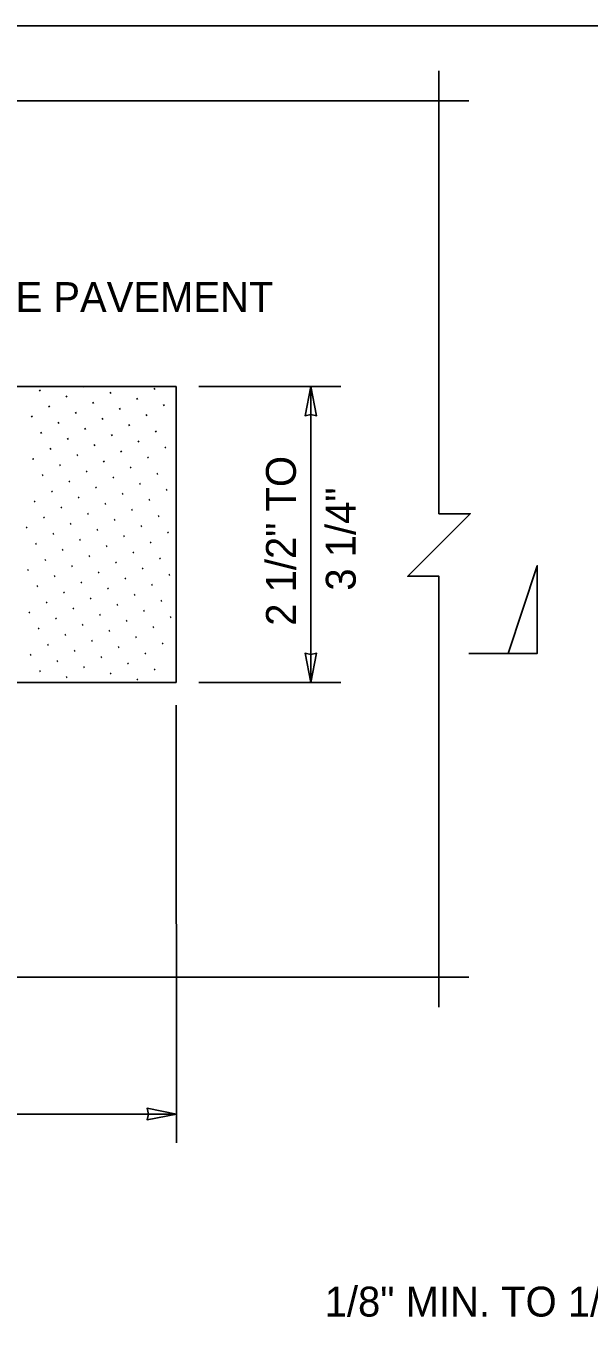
# Model space of a CAD drawing. Extents: x 99862 to 104211, y 98939 to 105076.
# Drawn here: x 102415 to 102716, y 104381 to 105076 of the extents above; entities that cross this region are included whole.
import ezdxf

# ---------------------------------------------------------------- set-up
doc = ezdxf.new("R2010")
doc.units = 0
for name, color, linetype in [('Level 1', 7, 'Continuous'), ('Level 15', 7, 'Continuous'), ('Level 20', 7, 'Continuous'), ('Level 3', 7, 'Continuous'), ('Level 9', 7, 'Continuous')]:
    doc.layers.add(name, color=color, linetype=linetype)

msp = doc.modelspace()

# ---------------------------------------------------------------- linework, layer by layer
at = {"layer": 'Level 1'}
for p, q in [((100264.63, 104882.79), (102495.44, 104882.79)), ((102495.44, 104882.79), (102495.44, 104724.41)), ((102495.44, 104724.41), (100264.63, 104724.41))]:
    msp.add_line(p, q, dxfattribs=at)
msp.add_lwpolyline([(99862, 102999.5), (103151, 102999.5), (103151, 105075.5), (99862, 105075.5)], close=True, dxfattribs=at)
for points in [[(102651.95, 105035.45), (102087.59, 105035.45), (102087.59, 105018.74), (102054.18, 105052.15), (102054.18, 105035.45), (101386.54, 105035.45)], [(102635.95, 105051.45), (102635.95, 104814.69), (102652.65, 104814.69), (102619.25, 104781.28), (102635.95, 104781.28), (102635.95, 104550.9)], [(102651.95, 104566.9), (102017.87, 104566.9), (102017.87, 104550.19), (101984.46, 104583.6), (101984.46, 104566.9), (101386.54, 104566.9)]]:
    msp.add_lwpolyline(points, dxfattribs=at)
at = {"layer": 'Level 15'}
for p, q in [((102507.44, 104882.79), (102583.41, 104882.79)), ((102567.41, 104882.79), (102567.41, 104724.41)), ((102507.44, 104724.41), (102583.41, 104724.41)), ((102495.44, 104712.41), (102495.5, 104478.38)), ((102495.51, 104493.74), (102057.49, 104493.74))]:
    msp.add_line(p, q, dxfattribs=at)
for points in [[(102567.41, 104882.79), (102564.33, 104867.07), (102567.41, 104867.8), (102570.5, 104867.07)], [(102567.41, 104724.41), (102564.33, 104740.13), (102567.41, 104739.41), (102570.5, 104740.13)], [(102495.51, 104493.74), (102479.78, 104490.66), (102480.51, 104493.74), (102479.78, 104496.83)]]:
    msp.add_lwpolyline(points, close=True, dxfattribs=at)
at = {"layer": 'Level 3'}
for p, q in [((102445.68, 104882.52), (102446.15, 104882.79)), ((102483.48, 104881.25), (102484.09, 104881.6)), ((102422.15, 104880.48), (102422.75, 104880.83)), ((102436.41, 104877.17), (102437.02, 104877.52)), ((102459.95, 104879.21), (102460.56, 104879.56)), ((102474.22, 104875.9), (102474.82, 104876.25)), ((102427.15, 104871.82), (102427.75, 104872.17)), ((102441.41, 104868.51), (102442.02, 104868.86)), ((102450.68, 104873.86), (102451.29, 104874.21)), ((102464.95, 104870.55), (102465.56, 104870.9)), ((102479.22, 104867.24), (102479.82, 104867.59)), ((102488.48, 104872.59), (102489.09, 104872.94)), ((102417.88, 104866.47), (102418.48, 104866.82)), ((102432.15, 104863.16), (102432.75, 104863.51)), ((102455.68, 104865.2), (102456.29, 104865.55)), ((102469.95, 104861.89), (102470.56, 104862.24)), ((102422.88, 104857.81), (102423.48, 104858.16)), ((102437.15, 104854.5), (102437.75, 104854.85)), ((102446.41, 104859.85), (102447.02, 104860.2)), ((102460.68, 104856.54), (102461.29, 104856.89)), ((102474.95, 104853.23), (102475.56, 104853.58)), ((102484.22, 104858.58), (102484.82, 104858.93)), ((102427.88, 104849.15), (102428.48, 104849.5)), ((102451.41, 104851.19), (102452.02, 104851.54)), ((102465.68, 104847.88), (102466.29, 104848.23)), ((102489.22, 104849.92), (102489.82, 104850.27)), ((102418.61, 104843.8), (102419.22, 104844.15)), ((102432.88, 104840.49), (102433.48, 104840.84)), ((102442.15, 104845.84), (102442.75, 104846.19)), ((102456.41, 104842.53), (102457.02, 104842.88)), ((102470.68, 104839.22), (102471.29, 104839.57)), ((102479.95, 104844.57), (102480.56, 104844.92)), ((102423.61, 104835.14), (102424.22, 104835.49)), ((102447.15, 104837.18), (102447.75, 104837.53)), ((102461.41, 104833.87), (102462.02, 104834.22)), ((102484.95, 104835.91), (102485.56, 104836.26)), ((102428.61, 104826.48), (102429.22, 104826.83)), ((102437.88, 104831.83), (102438.48, 104832.18)), ((102452.15, 104828.52), (102452.75, 104828.87)), ((102475.68, 104830.56), (102476.29, 104830.91)), ((102489.95, 104827.25), (102490.56, 104827.6)), ((102419.34, 104821.13), (102419.95, 104821.48)), ((102442.88, 104823.17), (102443.48, 104823.52)), ((102457.15, 104819.86), (102457.75, 104820.21)), ((102466.41, 104825.21), (102467.02, 104825.56)), ((102480.68, 104821.9), (102481.29, 104822.25)), ((102424.34, 104812.47), (102424.95, 104812.82)), ((102433.61, 104817.82), (102434.22, 104818.17)), ((102447.88, 104814.51), (102448.48, 104814.86)), ((102471.41, 104816.55), (102472.02, 104816.9)), ((102485.68, 104813.24), (102486.29, 104813.59)), ((102415.08, 104807.12), (102415.68, 104807.47)), ((102438.61, 104809.16), (102439.22, 104809.51)), ((102452.88, 104805.85), (102453.48, 104806.2)), ((102462.15, 104811.2), (102462.75, 104811.55)), ((102476.41, 104807.89), (102477.02, 104808.24)), ((102490.68, 104804.58), (102491.29, 104804.93)), ((102420.08, 104798.46), (102420.68, 104798.81)), ((102429.34, 104803.81), (102429.95, 104804.16)), ((102443.61, 104800.5), (102444.22, 104800.85)), ((102467.15, 104802.54), (102467.75, 104802.89)), ((102481.41, 104799.23), (102482.02, 104799.58)), ((102434.34, 104795.15), (102434.95, 104795.5)), ((102448.61, 104791.84), (102449.22, 104792.19)), ((102457.88, 104797.19), (102458.48, 104797.54)), ((102472.15, 104793.88), (102472.75, 104794.23)), ((102415.81, 104784.45), (102416.41, 104784.8)), ((102425.08, 104789.8), (102425.68, 104790.15)), ((102439.34, 104786.49), (102439.95, 104786.84)), ((102462.88, 104788.53), (102463.48, 104788.88)), ((102477.15, 104785.22), (102477.75, 104785.57)), ((102486.41, 104790.57), (102487.02, 104790.92)), ((102430.08, 104781.14), (102430.68, 104781.49)), ((102444.34, 104777.83), (102444.95, 104778.18)), ((102453.61, 104783.18), (102454.22, 104783.53)), ((102467.88, 104779.87), (102468.48, 104780.22)), ((102491.41, 104781.91), (102492.02, 104782.26)), ((102420.81, 104775.79), (102421.41, 104776.14)), ((102435.08, 104772.48), (102435.68, 104772.83)), ((102458.61, 104774.52), (102459.22, 104774.87)), ((102472.88, 104771.21), (102473.48, 104771.56)), ((102482.15, 104776.56), (102482.75, 104776.91)), ((102425.81, 104767.13), (102426.41, 104767.48)), ((102440.08, 104763.82), (102440.68, 104764.17)), ((102449.34, 104769.17), (102449.95, 104769.52)), ((102463.61, 104765.86), (102464.22, 104766.21)), ((102487.15, 104767.9), (102487.75, 104768.25)), ((102416.54, 104761.78), (102417.15, 104762.13)), ((102430.81, 104758.47), (102431.41, 104758.82)), ((102454.34, 104760.51), (102454.95, 104760.86)), ((102468.61, 104757.2), (102469.22, 104757.55)), ((102477.88, 104762.55), (102478.48, 104762.9)), ((102492.15, 104759.24), (102492.75, 104759.59)), ((102421.54, 104753.12), (102422.15, 104753.47)), ((102435.81, 104749.81), (102436.41, 104750.16)), ((102445.08, 104755.16), (102445.68, 104755.51)), ((102459.34, 104751.85), (102459.95, 104752.2)), ((102482.88, 104753.89), (102483.48, 104754.24)), ((102426.54, 104744.45), (102427.15, 104744.8)), ((102450.08, 104746.5), (102450.68, 104746.85)), ((102464.34, 104743.19), (102464.95, 104743.54)), ((102473.61, 104748.54), (102474.22, 104748.89)), ((102487.88, 104745.23), (102488.48, 104745.58)), ((102417.27, 104739.1), (102417.88, 104739.45)), ((102431.54, 104735.79), (102432.15, 104736.14)), ((102440.81, 104741.15), (102441.41, 104741.5)), ((102455.08, 104737.84), (102455.68, 104738.19)), ((102478.61, 104739.88), (102479.22, 104740.23)), ((102422.27, 104730.44), (102422.88, 104730.79)), ((102445.81, 104732.49), (102446.41, 104732.84)), ((102460.08, 104729.18), (102460.68, 104729.53)), ((102469.34, 104734.53), (102469.95, 104734.88)), ((102483.61, 104731.22), (102484.22, 104731.57)), ((102436.54, 104727.13), (102437.15, 104727.48)), ((102474.34, 104725.87), (102474.95, 104726.22))]:
    msp.add_line(p, q, dxfattribs=at)
at = {"layer": 'Level 9'}
msp.add_line((102651.95, 104740.02), (102688.47, 104740.02), dxfattribs=at)
msp.add_lwpolyline([(102672.95, 104740.02), (102688.47, 104786.9), (102688.47, 104740.02)], close=True, dxfattribs=at)

# ---------------------------------------------------------------- texts
at = {"layer": 'Level 20'}
for s, p in [('EXISTING CEMENT CONCRETE PAVEMENT', (102101.58, 104922.53)), ('1/8" MIN. TO 1/4" MAX. DEPTH OF ', (102574.8, 104385.47))]:
    msp.add_text(s, height=16, dxfattribs=at).set_placement(p)
for s, p in [('2 1/2" TO', (102559.41, 104754.79)), ('3 1/4"', (102591.41, 104773.58))]:
    msp.add_text(s, height=16, rotation=90, dxfattribs=at).set_placement(p)

doc.saveas('drawing.dxf')
